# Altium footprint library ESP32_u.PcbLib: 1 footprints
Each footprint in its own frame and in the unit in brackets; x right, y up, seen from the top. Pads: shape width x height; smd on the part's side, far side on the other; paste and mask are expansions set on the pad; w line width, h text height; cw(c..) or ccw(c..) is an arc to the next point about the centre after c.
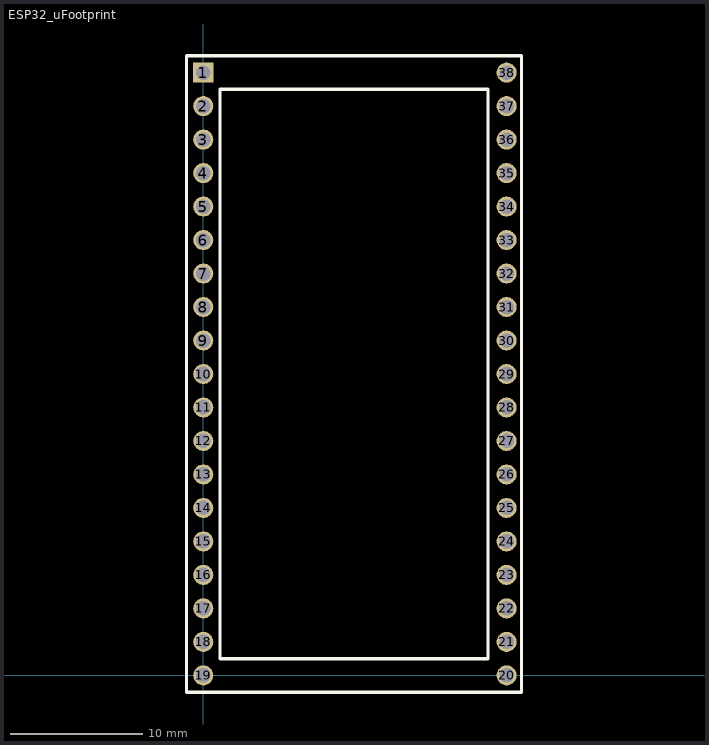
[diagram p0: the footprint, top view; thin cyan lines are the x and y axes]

## ESP32_uFootprint [mil] "This is a custom footprint made by Team RAW. The library is dedicated for ESP32_u"
height 511.81
pads (38):
  rect 60x60 hole 43.31: 1(0,1800)
  round 60 hole 43.31: 2(0,1700) 3(0,1600) 4(0,1500) 5(0,1400) 6(0,1300) 7(0,1200) 8(0,1100) 9(0,1000) 10(0,900) 11(0,800) 12(0,700) 13(0,600) 14(0,500) 15(0,400) 16(0,300) 17(0,200) 18(0,100) 19(0,0) 20(905.51,0) 21(905.51,100) 22(905.51,200) 23(905.51,300) 24(905.51,400) 25(905.51,500) 26(905.51,600) 27(905.51,700) 28(905.51,800) 29(905.51,900) 30(905.51,1000) 31(905.51,1100) 32(905.51,1200) 33(905.51,1300) 34(905.51,1400) 35(905.51,1500) 36(905.51,1600) 37(905.51,1700) 38(905.51,1800)
Top Overlay:
  lines w10: -50,-50 -50,1850 950,1850 950,-50 -50,-50 ; 50,50 850,50 850,1750 50,1750 50,50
